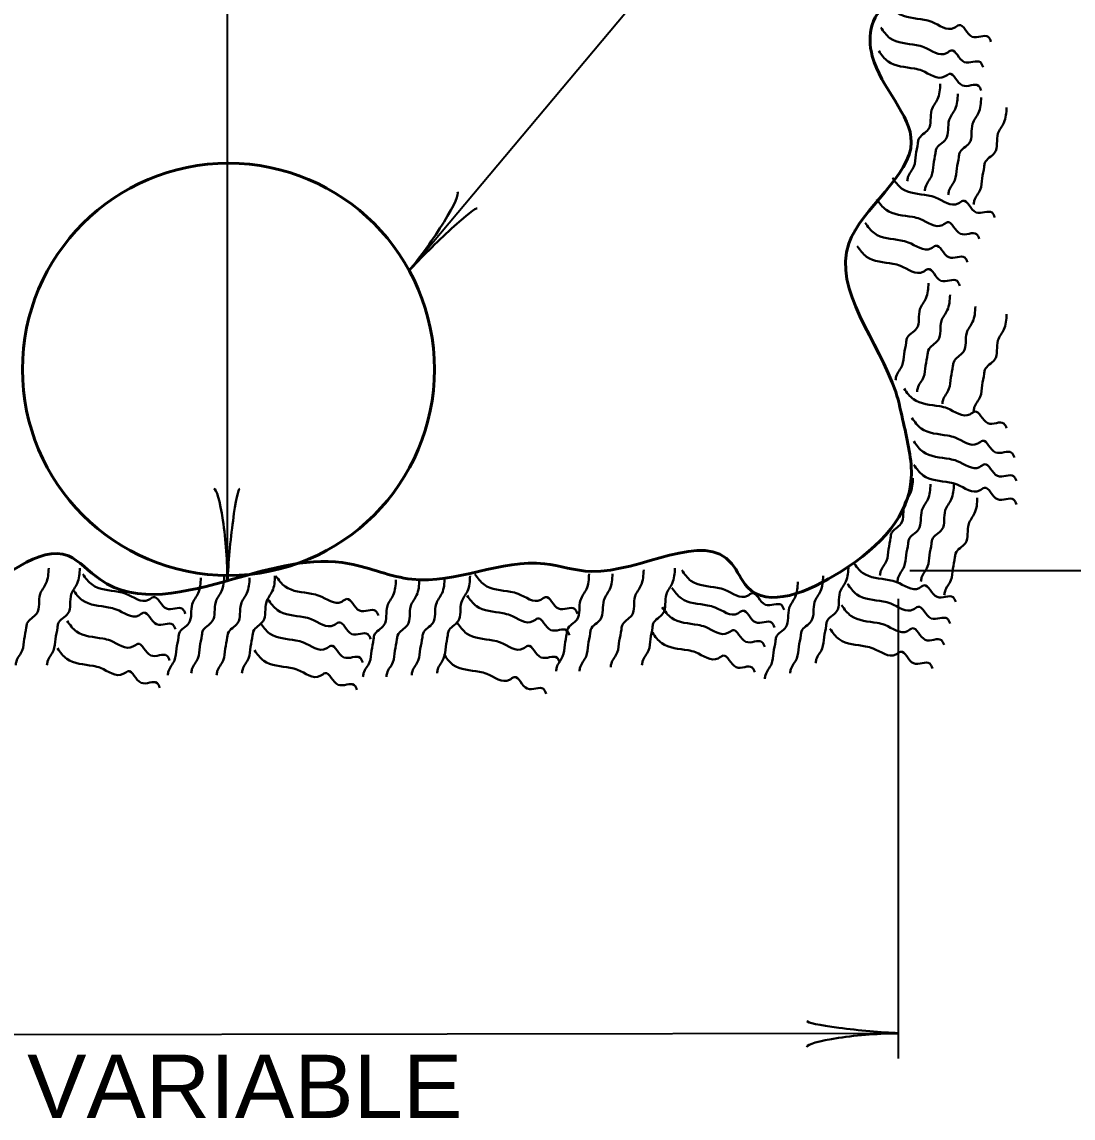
# Model space of a CAD drawing. Extents: x -617 to 238, y 23 to 567.
# Drawn here: x -239.08 to -199.27, y 249.05 to 290.53 of the extents above; entities that cross this region are included whole.
import ezdxf
from ezdxf.enums import TextEntityAlignment as Align

# ---------------------------------------------------------------- set-up
doc = ezdxf.new("R2010")
doc.units = 0
doc.header["$LTSCALE"] = 0.96
doc.layers.add('1', color=7, linetype='Continuous', lineweight=40)

msp = doc.modelspace()

# ---------------------------------------------------------------- linework, layer by layer
at = {"layer": '1', "lineweight": 35}
for p, q in [((-231.291, 269.4176), (-231.291, 316.6626)), ((-205.4564, 269.7739), (-165.8564, 269.7739)), ((-205.8996, 268.7029), (-205.8996, 251.3029)), ((-255.2456, 252.1937), (-205.8996, 252.2659))]:
    msp.add_line(p, q, dxfattribs=at)
msp.add_lwpolyline([(-224.4112, 281.1268), (-209.5319, 298.8592), (-213.7319, 298.8592)], dxfattribs=at)
at = {"layer": '1', "lineweight": 53}
msp.add_circle((-231.256, 277.3866), 7.8, dxfattribs=at)
at = {"layer": '1'}
for centre, major_axis, ratio, start_param, end_param in [((-223.8235, 282.343), (-1.2339, -1.762), 0.122415, 0.8963533, 3.1415927), ((-223.3524, 281.9936), (1.5163, 1.4791), 0.07063, 6.2823074, 8.5597026), ((-231.6226, 270.727), (0.1874, -2.1428), 0.122415, 0.8963533, 3.1415927), ((-231.6226, 270.727), (0.1874, -2.1428), 0.122415, 0.8963533, 3.1415927), ((-231.0371, 270.7622), (0.2108, 2.1077), 0.07063, 6.2823074, 8.5597026), ((-231.0371, 270.7622), (0.2108, 2.1077), 0.07063, 6.2823074, 8.5597026), ((-207.2446, 252.5179), (2.108, -0.2077), 0.07063, 3.1407148, 5.41811), ((-207.2086, 251.9324), (2.1426, 0.1905), 0.122415, 0.8963533, 3.1415927)]:
    msp.add_ellipse(centre, major_axis=major_axis, ratio=ratio, start_param=start_param, end_param=end_param, dxfattribs=at)
at = {"layer": '1', "lineweight": 53}
msp.add_spline([(-255.291, 382.6114), (-255.9281, 375.2243), (-254.7461, 372.2695), (-255.9281, 369.6102), (-255.0416, 367.2463), (-255.9281, 363.9961), (-254.7461, 361.9277), (-254.4506, 359.2684), (-254.7461, 355.1316), (-255.0416, 353.0633), (-256.2235, 351.5858), (-256.519, 350.6994), (-255.9281, 349.222), (-255.6326, 347.4491), (-255.3371, 345.3807), (-255.0416, 343.3124), (-255.0416, 340.9485), (-253.8597, 337.6982), (-254.1552, 335.6299), (-254.7461, 334.4479), (-254.7461, 331.1977), (-254.4506, 327.3564), (-254.7461, 325.879), (-254.7461, 322.6287), (-255.3371, 318.492), (-255.3371, 315.5372), (-256.519, 311.6959), (-255.6326, 309.6275), (-255.9281, 306.9682), (-256.2235, 303.7179), (-255.9281, 301.6495), (-255.6326, 298.1038), (-255.3371, 296.0354), (-255.6326, 293.6716), (-255.6326, 289.8303), (-254.7461, 288.9439), (-255.3371, 284.2162), (-255.3371, 281.5568), (-255.0416, 279.7839), (-255.6326, 276.2382), (-255.0416, 274.7608), (-255.6326, 272.1014), (-255.0416, 270.9195), (-252.6778, 268.5557), (-250.6094, 269.1466), (-248.541, 270.624), (-246.7681, 269.1466), (-244.9953, 268.8511), (-241.154, 268.8511), (-237.3127, 270.3286), (-236.1308, 269.4421), (-231.1076, 269.4421), (-226.6754, 270.0331), (-224.3116, 269.4421), (-219.2884, 270.0331), (-217.5155, 269.7376), (-212.1969, 270.0331), (-211.6059, 269.1466), (-208.0601, 269.7376), (-205.4008, 273.2834), (-205.6963, 275.3517), (-205.9918, 276.5337), (-207.7646, 282.1478), (-205.4008, 285.9891), (-206.8782, 289.2393), (-206.8782, 290.4213), (-205.6963, 292.4896), (-206.2872, 295.7399), (-205.4008, 297.2173), (-204.2189, 300.1721), (-205.9918, 305.1953), (-205.9918, 306.9682), (-205.6963, 309.0366), (-206.5827, 311.6959), (-206.2872, 313.4688), (-206.5827, 316.7191), (-207.7646, 320.8558), (-205.9918, 324.1061), (-205.6963, 326.7654), (-205.4008, 331.1977), (-205.6963, 333.5615), (-206.5827, 335.6299), (-206.5827, 337.4028), (-206.2872, 340.9485), (-207.4692, 344.4943), (-207.7646, 347.7446), (-205.6963, 350.9949), (-206.5827, 353.3587), (-206.8782, 354.8361), (-205.4008, 358.3819), (-206.5827, 361.0412), (-206.5827, 366.0644), (-206.2872, 367.8373), (-205.9918, 369.6102), (-207.1737, 372.8605), (-207.4692, 374.6334), (-207.291, 382.6114)], degree=3, dxfattribs=at)
at = {"layer": '1'}
for points in [[(-206.2645, 291.2838), (-205.913, 290.8835), (-204.914, 290.6159), (-204.6286, 290.5395), (-203.7724, 290.31), (-203.5914, 290.4145), (-203.0969, 289.9762), (-202.488, 289.9658), (-202.3835, 289.785)], [(-206.56, 290.3235), (-206.2085, 289.9232), (-205.2095, 289.6556), (-204.9241, 289.5792), (-204.0679, 289.3497), (-203.8869, 289.4542), (-203.3924, 289.0159), (-202.7835, 289.0055), (-202.679, 288.8247)], [(-206.6339, 289.437), (-206.2824, 289.0367), (-205.2834, 288.7691), (-204.998, 288.6927), (-204.1418, 288.4632), (-203.9608, 288.5677), (-203.4663, 288.1294), (-202.8574, 288.119), (-202.7529, 287.9382)], [(-204.3045, 288.1884), (-204.4071, 287.6065), (-204.6295, 287.1957), (-204.7578, 286.4681), (-205.1259, 286.083), (-205.1514, 285.9376), (-205.2284, 285.501), (-205.3053, 285.0645), (-205.5279, 284.6538), (-205.5536, 284.5082)], [(-203.6396, 287.819), (-203.7422, 287.2371), (-203.9646, 286.8263), (-204.0929, 286.0987), (-204.461, 285.7136), (-204.4865, 285.5682), (-204.5635, 285.1316), (-204.6404, 284.6951), (-204.863, 284.2844), (-204.8887, 284.1388)], [(-202.7532, 287.6713), (-202.8558, 287.0894), (-203.0782, 286.6786), (-203.2065, 285.951), (-203.5746, 285.5659), (-203.6001, 285.4205), (-203.6771, 284.9839), (-203.754, 284.5474), (-203.9766, 284.1367), (-204.0023, 283.9911)], [(-201.7929, 287.3019), (-201.8955, 286.72), (-202.1179, 286.3092), (-202.2462, 285.5816), (-202.6143, 285.1965), (-202.6398, 285.0511), (-202.7168, 284.6145), (-202.7937, 284.178), (-203.0163, 283.7673), (-203.042, 283.6217)], [(-206.1168, 284.6354), (-205.7653, 284.2351), (-204.7663, 283.9675), (-204.4809, 283.8911), (-203.6247, 283.6616), (-203.4437, 283.7661), (-202.9492, 283.3278), (-202.3403, 283.3174), (-202.2358, 283.1366)], [(-206.7077, 283.8229), (-206.3562, 283.4226), (-205.3572, 283.155), (-205.0718, 283.0786), (-204.2156, 282.8491), (-204.0346, 282.9536), (-203.5401, 282.5153), (-202.9312, 282.5049), (-202.8267, 282.3241)], [(-207.151, 282.9364), (-206.7995, 282.5361), (-205.8005, 282.2685), (-205.5151, 282.1921), (-204.6589, 281.9626), (-204.4779, 282.0671), (-203.9834, 281.6288), (-203.3745, 281.6184), (-203.27, 281.4376)], [(-207.4464, 282.05), (-207.0949, 281.6497), (-206.0959, 281.3821), (-205.8105, 281.3057), (-204.9543, 281.0762), (-204.7733, 281.1807), (-204.2788, 280.7424), (-203.6699, 280.732), (-203.5654, 280.5512)], [(-204.7477, 280.6536), (-204.8503, 280.0717), (-205.0727, 279.6609), (-205.201, 278.9333), (-205.5691, 278.5482), (-205.5946, 278.4028), (-205.6716, 277.9662), (-205.7485, 277.5297), (-205.9711, 277.119), (-205.9968, 276.9734)], [(-203.9351, 280.2104), (-204.0377, 279.6285), (-204.2601, 279.2177), (-204.3884, 278.4901), (-204.7565, 278.105), (-204.782, 277.9596), (-204.859, 277.523), (-204.9359, 277.0865), (-205.1585, 276.6758), (-205.1842, 276.5302)], [(-202.9748, 279.7672), (-203.0774, 279.1853), (-203.2998, 278.7745), (-203.4281, 278.0469), (-203.7962, 277.6618), (-203.8217, 277.5164), (-203.8987, 277.0798), (-203.9756, 276.6433), (-204.1982, 276.2326), (-204.2239, 276.087)], [(-201.7929, 279.4717), (-201.8955, 278.8898), (-202.1179, 278.479), (-202.2462, 277.7514), (-202.6143, 277.3663), (-202.6398, 277.2209), (-202.7168, 276.7843), (-202.7937, 276.3478), (-203.0163, 275.9371), (-203.042, 275.7915)], [(-205.6735, 276.6574), (-205.322, 276.2571), (-204.323, 275.9895), (-204.0376, 275.9131), (-203.1814, 275.6836), (-203.0004, 275.7881), (-202.5059, 275.3498), (-201.897, 275.3394), (-201.7925, 275.1586)], [(-205.3781, 275.5493), (-205.0266, 275.149), (-204.0276, 274.8814), (-203.7422, 274.805), (-202.886, 274.5755), (-202.705, 274.68), (-202.2105, 274.2417), (-201.6016, 274.2313), (-201.4971, 274.0505)], [(-205.3042, 274.6629), (-204.9527, 274.2626), (-203.9537, 273.995), (-203.6683, 273.9186), (-202.8121, 273.6891), (-202.6311, 273.7936), (-202.1366, 273.3553), (-201.5277, 273.3449), (-201.4232, 273.1641)], [(-205.3042, 273.7764), (-204.9527, 273.3761), (-203.9537, 273.1085), (-203.6683, 273.0321), (-202.8121, 272.8026), (-202.6311, 272.9071), (-202.1366, 272.4688), (-201.5277, 272.4584), (-201.4232, 272.2776)], [(-205.3387, 273.2666), (-205.4413, 272.6847), (-205.6637, 272.2739), (-205.792, 271.5463), (-206.1601, 271.1612), (-206.1856, 271.0158), (-206.2626, 270.5792), (-206.3395, 270.1427), (-206.5621, 269.732), (-206.5878, 269.5864)], [(-204.6739, 273.0449), (-204.7765, 272.463), (-204.9989, 272.0522), (-205.1272, 271.3246), (-205.4953, 270.9395), (-205.5208, 270.7941), (-205.5978, 270.3575), (-205.6747, 269.921), (-205.8973, 269.5103), (-205.923, 269.3647)], [(-203.7874, 273.0449), (-203.89, 272.463), (-204.1124, 272.0522), (-204.2407, 271.3246), (-204.6088, 270.9395), (-204.6343, 270.7941), (-204.7113, 270.3575), (-204.7882, 269.921), (-205.0108, 269.5103), (-205.0365, 269.3647)], [(-202.901, 272.5279), (-203.0036, 271.946), (-203.226, 271.5352), (-203.3543, 270.8076), (-203.7224, 270.4225), (-203.7479, 270.2771), (-203.8249, 269.8405), (-203.9018, 269.404), (-204.1244, 268.9933), (-204.1501, 268.8477)], [(-207.5942, 270.083), (-207.2427, 269.6827), (-206.2437, 269.4151), (-205.9583, 269.3387), (-205.1021, 269.1092), (-204.9211, 269.2137), (-204.4266, 268.7754), (-203.8177, 268.765), (-203.7132, 268.5842)], [(-238.0632, 269.8684), (-238.1658, 269.2865), (-238.3882, 268.8757), (-238.5165, 268.1481), (-238.8846, 267.763), (-238.9101, 267.6176), (-238.9871, 267.181), (-239.064, 266.7445), (-239.2866, 266.3338), (-239.3123, 266.1882)], [(-236.8813, 269.8684), (-236.9839, 269.2865), (-237.2063, 268.8757), (-237.3346, 268.1481), (-237.7027, 267.763), (-237.7282, 267.6176), (-237.8052, 267.181), (-237.8821, 266.7445), (-238.1047, 266.3338), (-238.1304, 266.1882)], [(-236.7729, 269.6397), (-236.4214, 269.2394), (-235.4224, 268.9718), (-235.137, 268.8954), (-234.2808, 268.6659), (-234.0998, 268.7704), (-233.6053, 268.3321), (-232.9964, 268.3217), (-232.8919, 268.1409)], [(-221.9251, 269.6397), (-221.5736, 269.2394), (-220.5746, 268.9718), (-220.2892, 268.8954), (-219.433, 268.6659), (-219.252, 268.7704), (-218.7575, 268.3321), (-218.1486, 268.3217), (-218.0441, 268.1409)], [(-217.6011, 269.6469), (-217.7037, 269.065), (-217.9261, 268.6542), (-218.0544, 267.9266), (-218.4225, 267.5415), (-218.448, 267.3961), (-218.525, 266.9595), (-218.6019, 266.523), (-218.8245, 266.1123), (-218.8502, 265.9667)], [(-216.7147, 269.6469), (-216.8173, 269.065), (-217.0397, 268.6542), (-217.168, 267.9266), (-217.5361, 267.5415), (-217.5616, 267.3961), (-217.6386, 266.9595), (-217.7155, 266.523), (-217.9381, 266.1123), (-217.9638, 265.9667)], [(-215.5328, 269.7946), (-215.6354, 269.2127), (-215.8578, 268.8019), (-215.9861, 268.0743), (-216.3542, 267.6892), (-216.3797, 267.5438), (-216.4567, 267.1072), (-216.5336, 266.6707), (-216.7562, 266.26), (-216.7819, 266.1144)], [(-214.3509, 269.8685), (-214.4535, 269.2866), (-214.6759, 268.8758), (-214.8042, 268.1482), (-215.1723, 267.7631), (-215.1978, 267.6177), (-215.2748, 267.1811), (-215.3517, 266.7446), (-215.5743, 266.3339), (-215.6, 266.1883)], [(-214.0948, 269.7875), (-213.7433, 269.3872), (-212.7443, 269.1196), (-212.4589, 269.0432), (-211.6027, 268.8137), (-211.4217, 268.9182), (-210.9272, 268.4799), (-210.3183, 268.4695), (-210.2138, 268.2887)], [(-207.7764, 269.9424), (-207.879, 269.3605), (-208.1014, 268.9497), (-208.2297, 268.2221), (-208.5978, 267.837), (-208.6233, 267.6916), (-208.7003, 267.255), (-208.7772, 266.8185), (-208.9998, 266.4078), (-209.0255, 266.2622)], [(-232.3014, 269.4991), (-232.404, 268.9172), (-232.6264, 268.5064), (-232.7547, 267.7788), (-233.1228, 267.3937), (-233.1483, 267.2483), (-233.2253, 266.8117), (-233.3022, 266.3752), (-233.5248, 265.9645), (-233.5505, 265.8189)], [(-231.4149, 269.573), (-231.5175, 268.9911), (-231.7399, 268.5803), (-231.8682, 267.8527), (-232.2363, 267.4676), (-232.2618, 267.3222), (-232.3388, 266.8856), (-232.4157, 266.4491), (-232.6383, 266.0384), (-232.664, 265.8928)], [(-230.4546, 269.4991), (-230.5572, 268.9172), (-230.7796, 268.5064), (-230.9079, 267.7788), (-231.276, 267.3937), (-231.3015, 267.2483), (-231.3785, 266.8117), (-231.4554, 266.3752), (-231.678, 265.9645), (-231.7037, 265.8189)], [(-229.4943, 269.573), (-229.5969, 268.9911), (-229.8193, 268.5803), (-229.9476, 267.8527), (-230.3157, 267.4676), (-230.3412, 267.3222), (-230.4182, 266.8856), (-230.4951, 266.4491), (-230.7177, 266.0384), (-230.7434, 265.8928)], [(-229.4598, 269.5658), (-229.1083, 269.1655), (-228.1093, 268.8979), (-227.8239, 268.8215), (-226.9677, 268.592), (-226.7867, 268.6965), (-226.2922, 268.2582), (-225.6833, 268.2478), (-225.5788, 268.067)], [(-224.9143, 269.4252), (-225.0169, 268.8433), (-225.2393, 268.4325), (-225.3676, 267.7049), (-225.7357, 267.3198), (-225.7612, 267.1744), (-225.8382, 266.7378), (-225.9151, 266.3013), (-226.1377, 265.8906), (-226.1634, 265.745)], [(-224.0279, 269.4252), (-224.1305, 268.8433), (-224.3529, 268.4325), (-224.4812, 267.7049), (-224.8493, 267.3198), (-224.8748, 267.1744), (-224.9518, 266.7378), (-225.0287, 266.3013), (-225.2513, 265.8906), (-225.277, 265.745)], [(-223.0675, 269.4991), (-223.1701, 268.9172), (-223.3925, 268.5064), (-223.5208, 267.7788), (-223.8889, 267.3937), (-223.9144, 267.2483), (-223.9914, 266.8117), (-224.0683, 266.3752), (-224.2909, 265.9645), (-224.3166, 265.8189)], [(-222.1072, 269.573), (-222.2098, 268.9911), (-222.4322, 268.5803), (-222.5605, 267.8527), (-222.9286, 267.4676), (-222.9541, 267.3222), (-223.0311, 266.8856), (-223.108, 266.4491), (-223.3306, 266.0384), (-223.3563, 265.8928)], [(-209.6971, 269.3514), (-209.7997, 268.7695), (-210.0221, 268.3587), (-210.1504, 267.6311), (-210.5185, 267.246), (-210.544, 267.1006), (-210.621, 266.664), (-210.6979, 266.2275), (-210.9205, 265.8168), (-210.9462, 265.6712)], [(-208.7368, 269.573), (-208.8394, 268.9911), (-209.0618, 268.5803), (-209.1901, 267.8527), (-209.5582, 267.4676), (-209.5837, 267.3222), (-209.6607, 266.8856), (-209.7376, 266.4491), (-209.9602, 266.0384), (-209.9859, 265.8928)], [(-207.8158, 269.2704), (-207.4643, 268.8701), (-206.4653, 268.6025), (-206.1799, 268.5261), (-205.3237, 268.2966), (-205.1427, 268.4011), (-204.6482, 267.9628), (-204.0393, 267.9524), (-203.9348, 267.7716)], [(-237.1423, 269.0487), (-236.7908, 268.6484), (-235.7918, 268.3808), (-235.5064, 268.3044), (-234.6502, 268.0749), (-234.4692, 268.1794), (-233.9747, 267.7411), (-233.3658, 267.7307), (-233.2613, 267.5499)], [(-222.2205, 268.8271), (-221.869, 268.4268), (-220.87, 268.1592), (-220.5846, 268.0828), (-219.7284, 267.8533), (-219.5474, 267.9578), (-219.0529, 267.5195), (-218.444, 267.5091), (-218.3395, 267.3283)], [(-214.4642, 269.1226), (-214.1127, 268.7223), (-213.1137, 268.4547), (-212.8283, 268.3783), (-211.9721, 268.1488), (-211.7911, 268.2533), (-211.2966, 267.815), (-210.6877, 267.8046), (-210.5832, 267.6238)], [(-229.7553, 268.6794), (-229.4038, 268.2791), (-228.4048, 268.0115), (-228.1194, 267.9351), (-227.2632, 267.7056), (-227.0822, 267.8101), (-226.5877, 267.3718), (-225.9788, 267.3614), (-225.8743, 267.1806)], [(-214.8335, 268.3839), (-214.482, 267.9836), (-213.483, 267.716), (-213.1976, 267.6396), (-212.3414, 267.4101), (-212.1604, 267.5146), (-211.6659, 267.0763), (-211.057, 267.0659), (-210.9525, 266.8851)], [(-208.0374, 268.4578), (-207.6859, 268.0575), (-206.6869, 267.7899), (-206.4015, 267.7135), (-205.5453, 267.484), (-205.3643, 267.5885), (-204.8698, 267.1502), (-204.2609, 267.1398), (-204.1564, 266.959)], [(-237.3639, 267.8668), (-237.0124, 267.4665), (-236.0134, 267.1989), (-235.728, 267.1225), (-234.8718, 266.893), (-234.6908, 266.9975), (-234.1963, 266.5592), (-233.5874, 266.5488), (-233.4829, 266.368)], [(-230.0508, 267.7929), (-229.6993, 267.3926), (-228.7003, 267.125), (-228.4149, 267.0486), (-227.5587, 266.8191), (-227.3777, 266.9236), (-226.8832, 266.4853), (-226.2743, 266.4749), (-226.1698, 266.2941)], [(-222.5899, 267.7929), (-222.2384, 267.3926), (-221.2394, 267.125), (-220.954, 267.0486), (-220.0978, 266.8191), (-219.9168, 266.9236), (-219.4223, 266.4853), (-218.8134, 266.4749), (-218.7089, 266.2941)], [(-208.4806, 267.5714), (-208.1291, 267.1711), (-207.1301, 266.9035), (-206.8447, 266.8271), (-205.9885, 266.5976), (-205.8075, 266.7021), (-205.313, 266.2638), (-204.7041, 266.2534), (-204.5996, 266.0726)], [(-215.2029, 267.4236), (-214.8514, 267.0233), (-213.8524, 266.7557), (-213.567, 266.6793), (-212.7108, 266.4498), (-212.5298, 266.5543), (-212.0353, 266.116), (-211.4264, 266.1056), (-211.3219, 265.9248)], [(-237.7332, 266.8326), (-237.3817, 266.4323), (-236.3827, 266.1647), (-236.0973, 266.0883), (-235.2411, 265.8588), (-235.0601, 265.9633), (-234.5656, 265.525), (-233.9567, 265.5146), (-233.8522, 265.3338)], [(-230.2724, 266.7587), (-229.9209, 266.3584), (-228.9219, 266.0908), (-228.6365, 266.0144), (-227.7803, 265.7849), (-227.5993, 265.8894), (-227.1048, 265.4511), (-226.4959, 265.4407), (-226.3914, 265.2599)], [(-223.107, 266.611), (-222.7555, 266.2107), (-221.7565, 265.9431), (-221.4711, 265.8667), (-220.6149, 265.6372), (-220.4339, 265.7417), (-219.9394, 265.3034), (-219.3305, 265.293), (-219.226, 265.1122)]]:
    msp.add_spline(points, degree=3, dxfattribs=at)

# ---------------------------------------------------------------- texts
at = {"layer": '1', "width": 1.05}
msp.add_text('VARIABLE', height=2.4, dxfattribs=at).set_placement((-230.6375, 249.0532), align=Align.CENTER)

doc.saveas('drawing.dxf')
